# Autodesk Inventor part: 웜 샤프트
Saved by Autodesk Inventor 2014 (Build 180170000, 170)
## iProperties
Created: 2025-06
Part Number: 웜 샤프트
Material: 일반
Document SubType Name: Modeling
Designer: dg
Density: 1 g/cm^3
Appearance: 기본값
Author: dg
Author: jhkim
Creation Date: 2025-05-23
Sending System: Autodesk Inventor 2026
Preprocessor: ST-DEVELOPER v20.1
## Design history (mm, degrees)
node "웜 샤프트1"
body "Solid1"
node "기준1"
